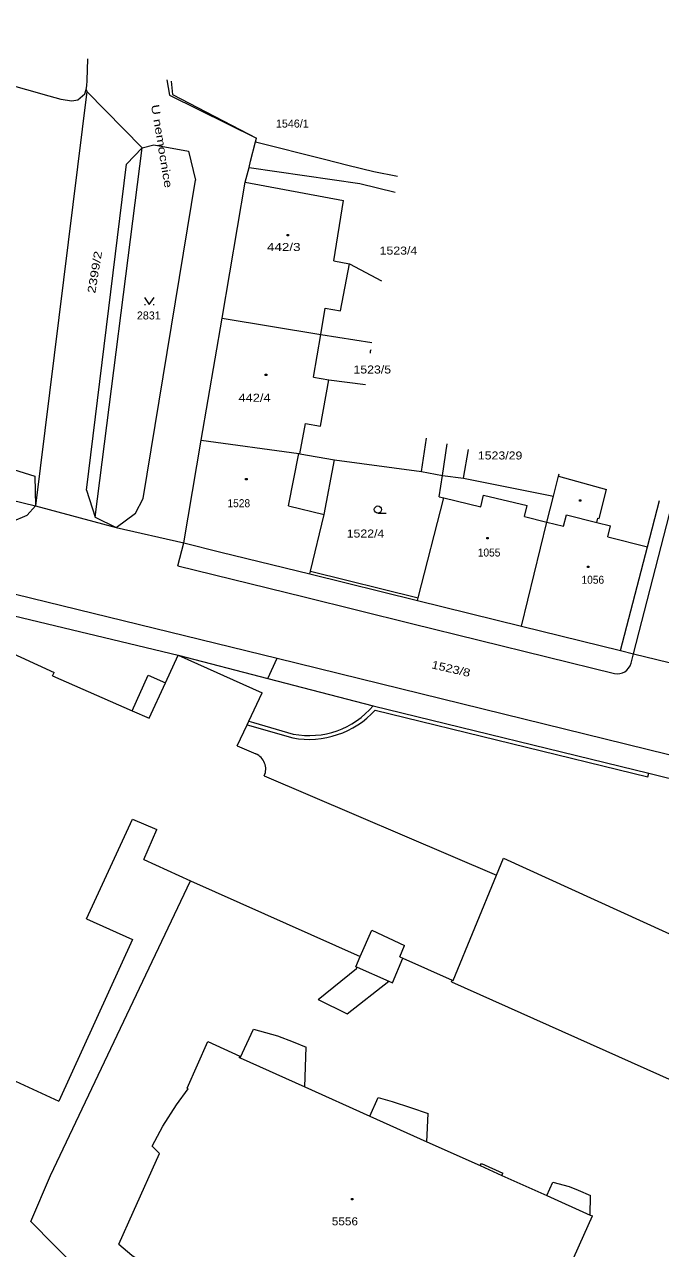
# Model space of a CAD drawing. Extents: x -630464 to -630140, y -1004543 to -1004208.
# Drawn here: x -630330.5 to -630262.9, y -1004346.3 to -1004216.3 of the extents above; entities that cross this region are included whole.
import ezdxf

# ---------------------------------------------------------------- set-up
doc = ezdxf.new("R2010")
doc.units = 0
doc.header["$LTSCALE"] = 0.34
for name, color, linetype, lineweight in [('1', 7, 'Continuous', 13), ('2', 7, 'Continuous', 13), ('23', 7, 'Continuous', 13), ('25', 7, 'Continuous', 13)]:
    doc.layers.add(name, color=color, linetype=linetype, lineweight=lineweight)
for name, color, linetype in [('14', 7, 'Continuous'), ('15', 7, 'Continuous'), ('38', 7, 'Continuous')]:
    doc.layers.add(name, color=color, linetype=linetype)

msp = doc.modelspace()

# ---------------------------------------------------------------- linework, layer by layer
at = {"layer": '1'}
for p, q in [((-630323.82, -1004222.26), (-630323.76, -1004219.949)), ((-630315.354, -1004222.196), (-630315.09, -1004223.8)), ((-630323.87, -1004223.43), (-630329.31, -1004267.44)), ((-630315.09, -1004223.8), (-630305.85, -1004228.4)), ((-630305.94, -1004228.77), (-630305.85, -1004228.4)), ((-630322.96, -1004268.64), (-630317.98, -1004229.42)), ((-630293.38, -1004231.93), (-630290.854, -1004232.438)), ((-630317.89, -1004266.65), (-630312.3, -1004232.85)), ((-630294.85, -1004233.2), (-630291.117, -1004234.137)), ((-630297.61, -1004241.43), (-630296.61, -1004235.01)), ((-630297.61, -1004241.43), (-630295.97, -1004241.74)), ((-630295.97, -1004241.74), (-630292.571, -1004243.538)), ((-630299.8, -1004253.77), (-630299.01, -1004249.23)), ((-630299.01, -1004249.23), (-630293.585, -1004250.093)), ((-630299.8, -1004253.77), (-630298.16, -1004254.05)), ((-630298.16, -1004254.05), (-630294.274, -1004254.543)), ((-630313.55, -1004271.37), (-630311.7, -1004260.46)), ((-630286.09, -1004264.22), (-630285.578, -1004260.846)), ((-630283.85, -1004264.5), (-630283.309, -1004261.452)), ((-630286.44, -1004266.47), (-630286.09, -1004264.22)), ((-630283.85, -1004264.5), (-630274.29, -1004266.42)), ((-630273.75, -1004264.29), (-630273.683, -1004264.025)), ((-630286.44, -1004266.47), (-630285.93, -1004266.59)), ((-630264.32, -1004271.8), (-630263.025, -1004266.873)), ((-630322.96, -1004268.64), (-630320.75, -1004269.74)), ((-630320.75, -1004269.74), (-630313.55, -1004271.37)), ((-630313.55, -1004271.37), (-630309.62, -1004272.34)), ((-630309.62, -1004272.34), (-630300.16, -1004274.67)), ((-630267.19, -1004282.8), (-630264.32, -1004271.8)), ((-630333.92, -1004278.57), (-630314.14, -1004283.28)), ((-630314.14, -1004283.28), (-630305.25, -1004287.29)), ((-630314.14, -1004283.28), (-630304.62, -1004285.77)), ((-630304.62, -1004285.77), (-630303.66, -1004283.61)), ((-630304.62, -1004285.77), (-630293.45, -1004288.67)), ((-630293.45, -1004288.67), (-630264.17, -1004295.83)), ((-630307.88, -1004292.93), (-630306.83, -1004290.68)), ((-630307.88, -1004292.93), (-630305.91, -1004293.78)), ((-630305.01, -1004296.1), (-630280.34, -1004306.66)), ((-630264.17, -1004295.83), (-630236.47, -1004302.62)), ((-630280.34, -1004306.66), (-630279.59, -1004304.85)), ((-630312.83, -1004307.28), (-630294.84, -1004315.3)), ((-630295.29, -1004316.39), (-630294.84, -1004315.3)), ((-630290.28, -1004315.49), (-630285.04, -1004317.8)), ((-630299.28, -1004319.85), (-630295.2, -1004316.57)), ((-630295.29, -1004316.39), (-630295.15, -1004316.45)), ((-630295.2, -1004316.57), (-630295.15, -1004316.45)), ((-630296.2, -1004321.39), (-630291.8, -1004317.93)), ((-630285.12, -1004317.98), (-630285.04, -1004317.8)), ((-630285.12, -1004317.98), (-630251.86, -1004332.87)), ((-630299.28, -1004319.85), (-630296.2, -1004321.39)), ((-630313.19, -1004329.3), (-630310.99, -1004324.34)), ((-630310.99, -1004324.34), (-630307.61, -1004325.89)), ((-630300.72, -1004329.16), (-630300.57, -1004324.93)), ((-630307.67, -1004326.02), (-630307.61, -1004325.89)), ((-630314.32, -1004331.05), (-630313.08, -1004329.35)), ((-630313.19, -1004329.3), (-630313.08, -1004329.35)), ((-630287.74, -1004334.97), (-630287.62, -1004331.98)), ((-630316.92, -1004335.44), (-630316.14, -1004336.22)), ((-630279.77, -1004338.55), (-630279.67, -1004338.31)), ((-630279.77, -1004338.55), (-630275, -1004340.69)), ((-630270.4, -1004342.76), (-630270.38, -1004340.69)), ((-630270.4, -1004342.76), (-630270.17, -1004342.86))]:
    msp.add_line(p, q, dxfattribs=at)
for points in [[(-630355.58, -1004216.31), (-630354.52, -1004216.45), (-630337.4, -1004221.2), (-630327.89, -1004223.88), (-630326.61, -1004224.26), (-630325.46, -1004224.42), (-630324.8, -1004224.32), (-630324.07, -1004223.66), (-630323.93, -1004223.2), (-630323.87, -1004223.43), (-630317.98, -1004229.42)], [(-630323.93, -1004223.2), (-630323.86, -1004222.84), (-630323.82, -1004222.26)], [(-630306.6, -1004231.5), (-630306.46, -1004230.83), (-630305.94, -1004228.77), (-630298.61, -1004230.61), (-630296.13, -1004231.24), (-630293.38, -1004231.93)], [(-630317.98, -1004229.42), (-630316.75, -1004229.1), (-630313.07, -1004229.78), (-630312.3, -1004232.85)], [(-630307.04, -1004233.05), (-630306.6, -1004231.5), (-630294.85, -1004233.2)], [(-630309.49, -1004247.49), (-630307.04, -1004233.05), (-630296.61, -1004235.01)], [(-630311.7, -1004260.46), (-630309.49, -1004247.49), (-630299.01, -1004249.23)], [(-630357.43, -1004260.68), (-630353.06, -1004261.66), (-630329.31, -1004267.44), (-630320.75, -1004269.74)], [(-630311.7, -1004260.46), (-630301.33, -1004261.89), (-630301.24, -1004261.91), (-630297.55, -1004262.55)], [(-630300.16, -1004274.67), (-630300.09, -1004274.37), (-630298.66, -1004268.37), (-630297.55, -1004262.55), (-630288.3, -1004263.79), (-630286.09, -1004264.22)], [(-630381.7, -1004264.98), (-630362.75, -1004269.45), (-630343.38, -1004274.04), (-630333.03, -1004276.43), (-630303.66, -1004283.61)], [(-630277.71, -1004280.2), (-630274.99, -1004269.16), (-630274.29, -1004266.42), (-630273.75, -1004264.29)], [(-630320.75, -1004269.74), (-630318.7, -1004268.23), (-630317.89, -1004266.65)], [(-630288.74, -1004277.5), (-630288.67, -1004277.21), (-630285.93, -1004266.59)], [(-630300.16, -1004274.67), (-630288.74, -1004277.5), (-630277.71, -1004280.2), (-630267.19, -1004282.8), (-630265.79, -1004283.15), (-630260.85, -1004284.35), (-630259.41, -1004284.68), (-630254.31, -1004285.96)], [(-630306.83, -1004290.68), (-630306.66, -1004290.31), (-630305.25, -1004287.29)], [(-630279.59, -1004304.85), (-630259.96, -1004313.83), (-630259.08, -1004312.63)], [(-630329.82, -1004343.46), (-630327.7, -1004338.56), (-630312.83, -1004307.28)], [(-630291.8, -1004317.93), (-630291.41, -1004318.11), (-630290.28, -1004315.49)], [(-630307.67, -1004326.02), (-630307.58, -1004326.06), (-630306.16, -1004323), (-630303.62, -1004323.71), (-630301.94, -1004324.35), (-630300.57, -1004324.93)], [(-630300.72, -1004329.16), (-630293.79, -1004332.26), (-630292.91, -1004330.27), (-630291.43, -1004330.7), (-630289.47, -1004331.32), (-630287.62, -1004331.98)], [(-630316.92, -1004335.44), (-630315.77, -1004333.33), (-630314.32, -1004331.05)], [(-630287.74, -1004334.97), (-630282.09, -1004337.51), (-630281.95, -1004337.27), (-630279.67, -1004338.31)], [(-630320.45, -1004345.86), (-630318.94, -1004342.47), (-630316.14, -1004336.22)], [(-630275, -1004340.69), (-630274.36, -1004339.27), (-630272.63, -1004339.74), (-630271.66, -1004340.11), (-630270.38, -1004340.69)], [(-630273.46, -1004351.32), (-630273.07, -1004349.32), (-630270.17, -1004342.86)], [(-630329.82, -1004343.46), (-630324.8, -1004348.52), (-630279.86, -1004368.77)], [(-630320.45, -1004345.86), (-630319.08, -1004347.02), (-630317.08, -1004348.35)]]:
    msp.add_lwpolyline(points, dxfattribs=at)
msp.add_arc((-630306.598, -1004295.382), 1.743, 335.65596, 66.74968, dxfattribs=at)
at = {"layer": '2'}
for p, q in [((-630314.909, -1004222.315), (-630314.76, -1004223.76)), ((-630314.76, -1004223.76), (-630305.85, -1004228.4)), ((-630319.63, -1004231.13), (-630317.98, -1004229.42)), ((-630323.88, -1004265.77), (-630319.63, -1004231.13)), ((-630296.92, -1004246.71), (-630295.97, -1004241.74)), ((-630299.05, -1004258.98), (-630298.16, -1004254.05)), ((-630357.09, -1004255.65), (-630329.39, -1004264.29)), ((-630301.24, -1004261.91), (-630300.64, -1004258.69)), ((-630300.64, -1004258.69), (-630299.05, -1004258.98)), ((-630288.3, -1004263.79), (-630287.79, -1004260.255)), ((-630302.44, -1004267.43), (-630301.33, -1004261.89)), ((-630329.39, -1004264.29), (-630329.31, -1004267.44)), ((-630286.09, -1004264.22), (-630283.85, -1004264.5)), ((-630273.75, -1004264.29), (-630268.66, -1004265.69)), ((-630323.88, -1004265.77), (-630322.96, -1004268.64)), ((-630330.2, -1004268.41), (-630329.31, -1004267.44)), ((-630302.44, -1004267.43), (-630298.66, -1004268.37)), ((-630285.93, -1004266.59), (-630282.02, -1004267.53)), ((-630277.39, -1004268.58), (-630277.1, -1004267.4)), ((-630265.79, -1004283.15), (-630261.682, -1004267.232)), ((-630331.87, -1004269.15), (-630330.2, -1004268.41)), ((-630277.39, -1004268.58), (-630274.99, -1004269.16)), ((-630273.22, -1004269.61), (-630272.91, -1004268.38)), ((-630272.91, -1004268.38), (-630269.69, -1004269.19)), ((-630274.99, -1004269.16), (-630273.22, -1004269.61)), ((-630269.69, -1004269.19), (-630268.25, -1004269.56)), ((-630268.54, -1004270.73), (-630268.25, -1004269.56)), ((-630314.18, -1004273.8), (-630313.55, -1004271.37)), ((-630268.54, -1004270.73), (-630264.32, -1004271.8)), ((-630314.18, -1004273.8), (-630300.78, -1004277.09)), ((-630300.09, -1004274.37), (-630288.67, -1004277.21)), ((-630300.78, -1004277.09), (-630289.37, -1004279.93)), ((-630289.37, -1004279.93), (-630267.82, -1004285.23)), ((-630266.06, -1004284.16), (-630265.79, -1004283.15)), ((-630303.66, -1004283.61), (-630178.49, -1004314.45)), ((-630327.49, -1004285.49), (-630327.34, -1004285.15)), ((-630293.24, -1004289.14), (-630264.26, -1004296.22)), ((-630306.83, -1004290.68), (-630301.98, -1004292.08)), ((-630306.66, -1004290.31), (-630306.15, -1004290.45)), ((-630306.15, -1004290.45), (-630301.94, -1004291.68)), ((-630264.26, -1004296.22), (-630264.17, -1004295.83)), ((-630317.8, -1004305.01), (-630316.43, -1004301.8)), ((-630317.8, -1004305.01), (-630312.83, -1004307.28)), ((-630294.84, -1004315.3), (-630293.59, -1004312.5)), ((-630293.59, -1004312.5), (-630290.11, -1004314.14)), ((-630290.63, -1004315.33), (-630290.11, -1004314.14)), ((-630290.63, -1004315.33), (-630290.28, -1004315.49)), ((-630295.15, -1004316.45), (-630291.8, -1004317.93)), ((-630307.58, -1004326.06), (-630300.72, -1004329.16)), ((-630331.44, -1004328.53), (-630326.84, -1004330.65)), ((-630293.79, -1004332.26), (-630287.74, -1004334.97)), ((-630282.09, -1004337.51), (-630279.77, -1004338.55)), ((-630275, -1004340.69), (-630270.4, -1004342.76))]:
    msp.add_line(p, q, dxfattribs=at)
for points in [[(-630299.01, -1004249.23), (-630298.54, -1004246.44), (-630296.92, -1004246.71)], [(-630282.02, -1004267.53), (-630281.72, -1004266.29), (-630277.1, -1004267.4)], [(-630269.69, -1004269.19), (-630269.58, -1004268.75), (-630269.44, -1004268.78), (-630268.66, -1004265.69)], [(-630334.51, -1004282.03), (-630334.45, -1004281.89), (-630327.34, -1004285.15)], [(-630327.49, -1004285.49), (-630319.03, -1004289.21), (-630317.24, -1004290), (-630315.51, -1004286.24), (-630314.14, -1004283.28)], [(-630319.03, -1004289.21), (-630317.33, -1004285.43), (-630315.51, -1004286.24)], [(-630323.89, -1004311.31), (-630319.02, -1004300.7), (-630316.43, -1004301.8)], [(-630285.04, -1004317.8), (-630284.94, -1004317.85), (-630280.34, -1004306.66)], [(-630323.89, -1004311.31), (-630319, -1004313.5), (-630326.84, -1004330.65)]]:
    msp.add_lwpolyline(points, dxfattribs=at)
for centre, radius, start, end in [((-630267.499, -1004283.776), 1.489, 257.53776, 345.05764), ((-630300.271, -1004282.701), 9.534, 259.67113, 317.51315), ((-630300.278, -1004282.888), 8.947, 259.29762, 319.74474)]:
    msp.add_arc(centre, radius, start, end, dxfattribs=at)
at = {"layer": '23'}
for p, q in [((-630317.72, -1004246.04), (-630317.62, -1004246.04)), ((-630316.82, -1004246.04), (-630316.72, -1004246.04)), ((-630292.95, -1004268.2), (-630292.075, -1004268.2))]:
    msp.add_line(p, q, dxfattribs=at)
msp.add_lwpolyline([(-630317.72, -1004245.29), (-630317.22, -1004246.04), (-630316.72, -1004245.29)], dxfattribs=at)
msp.add_circle((-630292.95, -1004267.825), 0.375, dxfattribs=at)
msp.add_arc((-630293.27, -1004251.108), 0.502, 149.45777, 192.95233, dxfattribs=at)
at = {"layer": '25'}
for points in [[(-630302.59, -1004238.61), (-630302.44, -1004238.61), (-630302.44, -1004238.76), (-630302.59, -1004238.76)], [(-630304.9, -1004253.45), (-630304.75, -1004253.45), (-630304.75, -1004253.6), (-630304.9, -1004253.6)], [(-630306.99, -1004264.54), (-630306.84, -1004264.54), (-630306.84, -1004264.69), (-630306.99, -1004264.69)], [(-630271.53, -1004266.79), (-630271.38, -1004266.79), (-630271.38, -1004266.94), (-630271.53, -1004266.94)], [(-630281.37, -1004270.8), (-630281.22, -1004270.8), (-630281.22, -1004270.95), (-630281.37, -1004270.95)], [(-630270.69, -1004273.83), (-630270.54, -1004273.83), (-630270.54, -1004273.98), (-630270.69, -1004273.98)], [(-630295.74, -1004341), (-630295.59, -1004341), (-630295.59, -1004341.15), (-630295.74, -1004341.15)]]:
    msp.add_lwpolyline(points, close=True, dxfattribs=at)

# ---------------------------------------------------------------- texts
at = {"layer": '14'}
for s, p in [('1546/1', (-630303.77, -1004227.26)), ('2831', (-630318.54, -1004247.64))]:
    msp.add_text(s, height=0.85, dxfattribs=at).set_placement(p)
for s, rotation, width, p in [('2399/2', 80.543, 1.3, (-630322.972, -1004244.915)), ('1523/8', 347.026, 1.2, (-630287.31, -1004284.68))]:
    msp.add_text(s, height=0.85, rotation=rotation, dxfattribs=dict(at, width=width)).set_placement(p)
at = {"layer": '14', "width": 1.15}
for s, p in [('1523/4', (-630292.76, -1004240.75)), ('1523/5', (-630295.54, -1004253.38)), ('1523/29', (-630282.33, -1004262.51)), ('1522/4', (-630296.26, -1004270.8))]:
    msp.add_text(s, height=0.85, dxfattribs=at).set_placement(p)
at = {"layer": '15'}
for s, width, p in [('442/3', 1.25, (-630304.72, -1004240.37)), ('442/4', 1.2, (-630307.75, -1004256.38)), ('1528', 0.95, (-630308.92, -1004267.58)), ('1055', 0.95, (-630282.34, -1004272.82)), ('1056', 0.95, (-630271.32, -1004275.71)), ('5556', 1.1, (-630297.84, -1004343.85))]:
    msp.add_text(s, height=0.85, dxfattribs=dict(at, width=width)).set_placement(p)
at = {"layer": '38', "width": 1.35}
msp.add_text('U nemocnice', height=0.85, rotation=279.358, dxfattribs=at).set_placement((-630317.041, -1004224.884))

doc.saveas('drawing.dxf')
